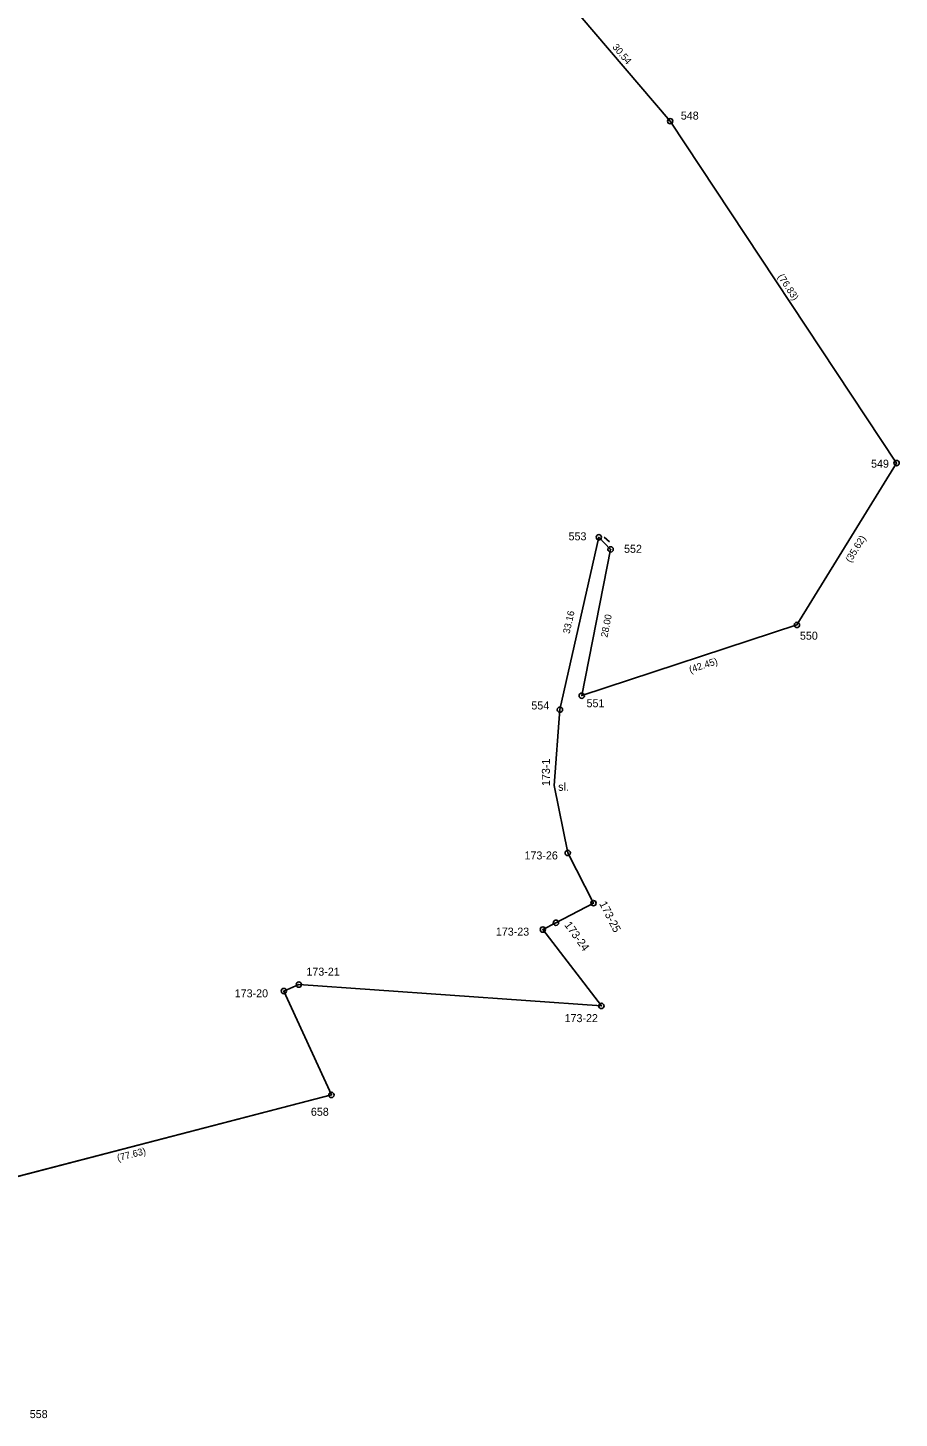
# Model space of a CAD drawing. Extents: x -555170 to -550532, y -1039598 to -1034701.
# Drawn here: x -553793.6 to -553630.3, y -1037741.5 to -1037480.9 of the extents above; entities that cross this region are included whole.
import ezdxf

# ---------------------------------------------------------------- set-up
doc = ezdxf.new("R2010")
doc.units = 0
for name, color, linetype in [('Vrstva 10', 7, 'Continuous'), ('Vrstva 40', 7, 'Continuous'), ('Vrstva 43', 7, 'Continuous'), ('Vrstva 48', 7, 'Continuous')]:
    doc.layers.add(name, color=color, linetype=linetype)

msp = doc.modelspace()

# ---------------------------------------------------------------- linework, layer by layer
at = {"layer": 'Vrstva 10'}
msp.add_line((-553684.54, -1037577.28), (-553685.53, -1037576.41), dxfattribs=at)
at = {"layer": 'Vrstva 40'}
for p, q in [((-553673.19, -1037498.45), (-553692.97, -1037475.2)), ((-553630.76, -1037562.51), (-553673.19, -1037498.45)), ((-553649.43, -1037592.85), (-553630.76, -1037562.51)), ((-553693.85, -1037608.72), (-553686.56, -1037576.41)), ((-553686.56, -1037576.41), (-553684.34, -1037578.68)), ((-553684.34, -1037578.68), (-553689.76, -1037606.1)), ((-553689.76, -1037606.1), (-553649.43, -1037592.85)), ((-553694.93, -1037622.92), (-553693.85, -1037608.72)), ((-553692.38, -1037635.58), (-553694.93, -1037622.92)), ((-553687.55, -1037644.98), (-553692.38, -1037635.58)), ((-553694.59, -1037648.65), (-553687.55, -1037644.98)), ((-553697.06, -1037649.93), (-553694.59, -1037648.65)), ((-553686.08, -1037664.24), (-553697.06, -1037649.93)), ((-553745.6, -1037661.46), (-553742.78, -1037660.25)), ((-553742.78, -1037660.25), (-553686.08, -1037664.24)), ((-553736.67, -1037680.93), (-553745.6, -1037661.46)), ((-553811.81, -1037700.43), (-553736.67, -1037680.93))]:
    msp.add_line(p, q, dxfattribs=at)
at = {"layer": 'Vrstva 43'}
for p, q in [((-553673.19, -1037498.45), (-553673.19, -1037498.45)), ((-553630.76, -1037562.51), (-553630.76, -1037562.51)), ((-553686.56, -1037576.41), (-553686.56, -1037576.41)), ((-553684.34, -1037578.68), (-553684.34, -1037578.68)), ((-553649.43, -1037592.85), (-553649.43, -1037592.85)), ((-553689.76, -1037606.1), (-553689.76, -1037606.1)), ((-553693.85, -1037608.72), (-553693.85, -1037608.72)), ((-553694.93, -1037622.92), (-553694.93, -1037622.92)), ((-553692.38, -1037635.58), (-553692.38, -1037635.58)), ((-553687.55, -1037644.98), (-553687.55, -1037644.98)), ((-553697.06, -1037649.93), (-553697.06, -1037649.93)), ((-553694.59, -1037648.65), (-553694.59, -1037648.65)), ((-553742.78, -1037660.25), (-553742.78, -1037660.25)), ((-553745.6, -1037661.46), (-553745.6, -1037661.46)), ((-553686.08, -1037664.24), (-553686.08, -1037664.24)), ((-553736.67, -1037680.93), (-553736.67, -1037680.93))]:
    msp.add_line(p, q, dxfattribs=at)
for centre, radius in [((-553673.19, -1037498.45), 0.5), ((-553673.19, -1037498.45), 0.01), ((-553630.76, -1037562.51), 0.5), ((-553630.76, -1037562.51), 0.01), ((-553686.56, -1037576.41), 0.5), ((-553686.56, -1037576.41), 0.01), ((-553684.34, -1037578.68), 0.5), ((-553684.34, -1037578.68), 0.01), ((-553649.43, -1037592.85), 0.5), ((-553649.43, -1037592.85), 0.01), ((-553689.76, -1037606.11), 0.5), ((-553689.76, -1037606.11), 0.01), ((-553693.85, -1037608.73), 0.5), ((-553693.85, -1037608.73), 0.01), ((-553692.38, -1037635.58), 0.5), ((-553692.38, -1037635.58), 0.01), ((-553687.55, -1037644.98), 0.5), ((-553687.55, -1037644.98), 0.01), ((-553697.06, -1037649.93), 0.5), ((-553697.06, -1037649.93), 0.01), ((-553694.59, -1037648.65), 0.5), ((-553694.59, -1037648.65), 0.01), ((-553742.78, -1037660.25), 0.5), ((-553742.78, -1037660.25), 0.01), ((-553745.6, -1037661.46), 0.5), ((-553745.6, -1037661.46), 0.01), ((-553686.08, -1037664.24), 0.5), ((-553686.08, -1037664.24), 0.01), ((-553736.67, -1037680.93), 0.5), ((-553736.67, -1037680.93), 0.01)]:
    msp.add_circle(centre, radius, dxfattribs=at)
at = {"layer": 'Vrstva 48'}
msp.add_lwpolyline([(-553692.97, -1037475.2), (-553673.19, -1037498.45), (-553630.76, -1037562.51), (-553649.43, -1037592.85), (-553689.76, -1037606.1), (-553684.34, -1037578.68), (-553686.56, -1037576.41), (-553693.85, -1037608.72), (-553694.93, -1037622.92), (-553692.38, -1037635.58), (-553687.55, -1037644.98), (-553694.59, -1037648.65), (-553697.06, -1037649.93), (-553686.08, -1037664.24), (-553742.78, -1037660.25), (-553745.6, -1037661.46), (-553736.67, -1037680.93), (-553811.81, -1037700.43)], dxfattribs=at)

# ---------------------------------------------------------------- texts
at = {"layer": 'Vrstva 10'}
for s, rotation, p in [('30.54', 310.3951, (-553684.11, -1037484.61)), ('(76.83)', 303.5152, (-553653.11, -1037527.58)), ('(35.62)', 58.398, (-553639.34, -1037581.26)), ('33.16', 77.288, (-553692.05, -1037594.59)), ('28.00', 78.8135, (-553684.95, -1037595.26)), ('(42.45)', 18.1985, (-553669.4, -1037601.88)), ('(77.63)', 14.5471, (-553776.67, -1037693.38))]:
    msp.add_text(s, height=1.3, rotation=rotation, dxfattribs=at).set_placement(p)
at = {"layer": 'Vrstva 43'}
for s, p in [('548', (-553671.19, -1037498.15)), ('549', (-553635.54, -1037563.38)), ('553', (-553692.23, -1037576.99)), ('552', (-553681.83, -1037579.33)), ('550', (-553648.87, -1037595.61)), ('554', (-553699.2, -1037608.69)), ('551', (-553688.86, -1037608.27)), ('sl.', (-553694.18, -1037623.93)), ('173-26', (-553700.49, -1037636.79)), ('173-23', (-553705.86, -1037651.07)), ('173-21', (-553741.36, -1037658.57)), ('173-20', (-553754.8, -1037662.63)), ('173-22', (-553692.98, -1037667.28)), ('658', (-553740.52, -1037684.83)), ('558', (-553793.21, -1037741.48))]:
    msp.add_text(s, height=1.5, dxfattribs=at).set_placement(p)
for s, rotation, p in [('173-1', 90, (-553695.73, -1037623.03)), ('173-25', 297, (-553686.52, -1037645.07)), ('173-24', 306, (-553693.09, -1037649.08))]:
    msp.add_text(s, height=1.5, rotation=rotation, dxfattribs=at).set_placement(p)

doc.saveas('drawing.dxf')
